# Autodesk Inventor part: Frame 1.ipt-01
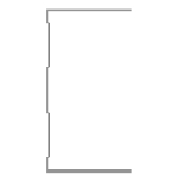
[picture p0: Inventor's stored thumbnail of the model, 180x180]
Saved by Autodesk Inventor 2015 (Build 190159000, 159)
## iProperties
Created: 2015-04
Part Number: Frame 1.ipt-01
Material: Aluminum 6061
Description: Kévin Novo
Document SubType Name: Modeling
Standard: Kevin
Designer: suporte
Standards Organization: Kevin
Language: en-US
Size Designation: (Unnamed 1)
Categories: <MemberInstance><Categories><Category DisplayName="Structural Shapes" InternalName="089c4875-fa83-4c05-b084-43b9cc11f5ed" Mnemonic="GRDR"><CategoryParameter Dis
Density: 2.7 g/cm^3
Appearance: Aluminum - Flat
_CCFamilyMember: 1
_CCFamilyDisplayName: Kévin - Kévin Novo
_FrameMemberDoc: Frame Member File
_Version: 15.0.0
_GetPNFromCC: 1
G_L: 1498,590 mm
G_W: 50,000 mm
G_H: 75,000 mm
+E6FCAD43-AC47-4BE5-B588-6C7439B0D930+CUTDETAIL1: Cut
+70689007-2E59-4765-8830-24DCB7203E4C+CUTDETAIL2: Cut
IsCustomPart: 1
Author: suporte
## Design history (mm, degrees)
node "Start Plane"
node "End Plane"
sketch "Sketch"
  geometry: L1 (24.7, 37.5)-(24.7, 36.9); L2 (24.7, 36.9)-(-24.7, 36.9); L3 (-24.7, -36.9)-(24.7, -36.9); L4 (24.7, -36.9)-(24.7, -37.5); L5 (24.7, -37.5)-(-25.3, -37.5); L6 (-25.3, 37.5)-(24.7, 37.5); L7 (-24.7, 36.9)-(-24.7, 31.9); L8 (-24.7, 31.9)-(-23.3, 30.5); L9 (-23.3, 30.5)-(-23.3, 10.934); L10 (-23.3, 10.934)-(-24.7, 9.534); L11 (-24.7, 9.534)-(-24.7, -9.534); L12 (-24.7, -9.534)-(-23.3, -10.934); L13 (-23.3, -10.934)-(-23.3, -30.5); L14 (-23.3, -30.5)-(-24.7, -31.9); L15 (-24.7, -31.9)-(-24.7, -36.9); L16 (-25.3, -37.5)-(-25.3, -31.651); L17 (-25.3, -31.651)-(-23.9, -30.251); L18 (-23.9, -30.251)-(-23.9, -11.183); L19 (-23.9, -11.183)-(-25.3, -9.783); L20 (-25.3, -9.783)-(-25.3, 9.783); L21 (-25.3, 9.783)-(-23.9, 11.183); L22 (-23.9, 11.183)-(-23.9, 30.251); L23 (-23.9, 30.251)-(-25.3, 31.651); L24 (-25.3, 31.651)-(-25.3, 37.5); L25 (-25.3, 0)-(30.37, 0); 3 further points
  constraints: 50 end point, 10 point on line, 9 parallel, 5 perpendicular, 4 equal length, 3 midpoint, 3 vertical, 2 vertical alignment, 1 collinear, 1 horizontal, 1 horizontal alignment
  dimensions: "d3" = 0.6 distance of L1.start L1.end (= d6); "d5" = 75 distance between parallel lines of L5 L6; "d6" = 0.6 distance between parallel lines of L24 L7 (= d8); "d7" = 0.6 distance between parallel lines of L8 L23 (= d8); "d8" = 0.6 distance between parallel lines of L22 L9 (= d12); "Espessura" = 0.6 distance between parallel lines of L17 L14; "d10" = 0.6 distance between parallel lines of L13 L18 (= Espessura); "d11" = 0.6 distance between parallel lines of L12 L19 (= Espessura); "d12" = 0.6 distance between parallel lines of L21 L10 (= d11); "d13" = 5 distance of L2.end L7.end; "d15" = 135 deg angle of L9 L8; "d16" = 2 distance between parallel lines of L24 L9; "d17" = 50 distance of L6.start L1.start
extrude "Body" join sketch "Sketch" stored distance "d24" = 0.13; taper "d25" = 0 deg
node "Driven Length"
  sketch "Sketch10"
    geometry: L1 (0, 0)-(10, 0) reference
    constraints: 2 end point, 1 horizontal
  workplane "Work Plane7"
  sketch "Sketch11"
    geometry: L1 (-2, -798.826)-(12, -798.826) reference; L2 (-2, 699.763)-(12, 699.763) reference
    dimensions: "d27" = 1498.58967 distance between parallel lines of L1 L2 (derived)
workplane "Work Plane8"
split "Split1"
workplane "Work Plane9"
split "Split2"
body "Solid1"
other parameters: "tamanho" = 724.76332, "G_OFFSET_START" = 798.82636 [user parameter; used in 1 equation term], "G_OFFSET_END" = -25 [user parameter; used in 1 equation term], "d22" = -798.82636 (= -G_OFFSET_START), "d23" = 699.76332 (= tamanho + G_OFFSET_END), "G_L" = 1498.58967 (= d27) [user parameter], "d34" = 90 deg
